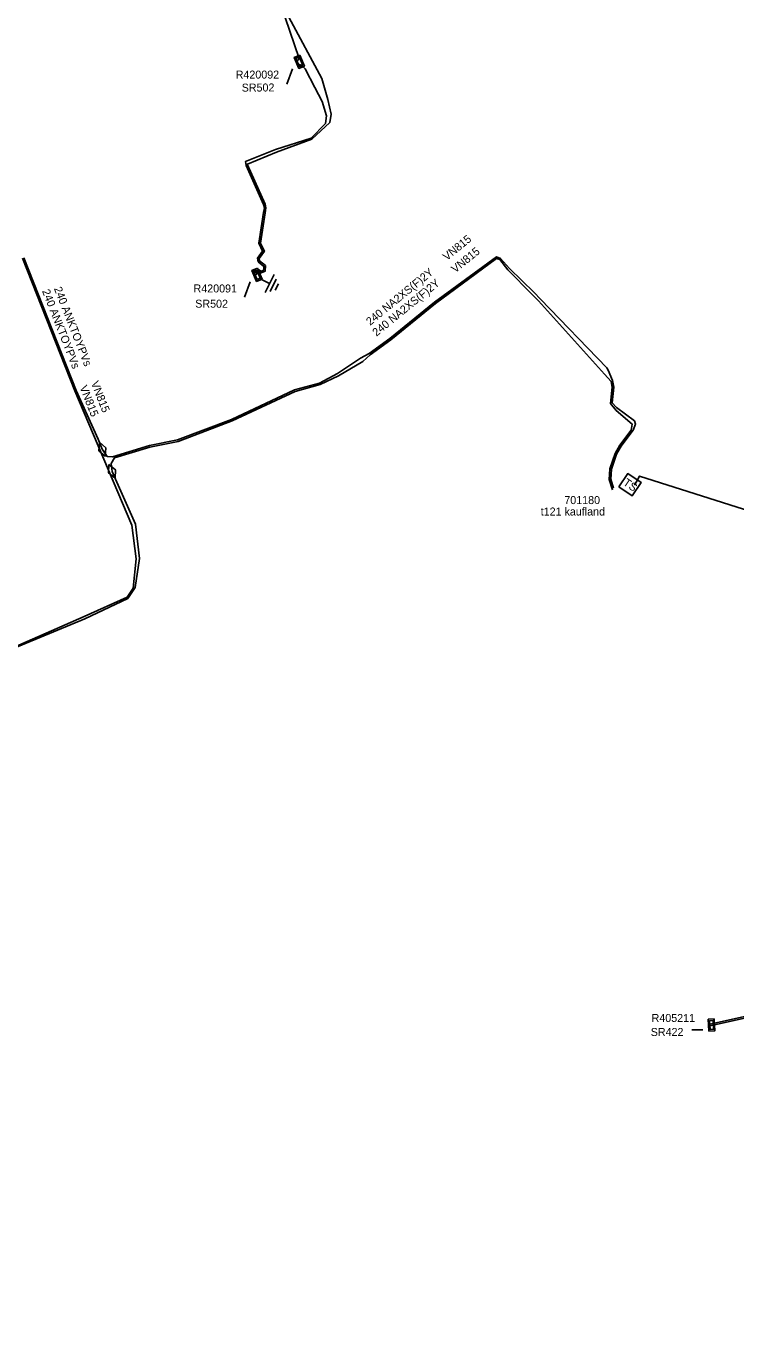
# Model space of a CAD drawing. Extents: x -540028 to -538776, y -1157064 to -1155670.
# Drawn here: x -539454.6 to -539365.9, y -1156092.2 to -1155928.9 of the extents above; entities that cross this region are included whole.
import ezdxf

# ---------------------------------------------------------------- set-up
doc = ezdxf.new("R2010")
doc.units = 0
for name, color, linetype in [('Vrstva 15', 7, 'Continuous'), ('Vrstva 19', 7, 'Continuous'), ('Vrstva 2', 7, 'Continuous'), ('Vrstva 25', 7, 'Continuous'), ('Vrstva 26', 7, 'Continuous'), ('Vrstva 27', 7, 'Continuous'), ('Vrstva 28', 7, 'Continuous'), ('Vrstva 29', 7, 'Continuous'), ('Vrstva 30', 7, 'Continuous'), ('Vrstva 5', 7, 'Continuous'), ('Vrstva 59', 7, 'Continuous'), ('Vrstva 6', 7, 'Continuous'), ('Vrstva 7', 7, 'Continuous')]:
    doc.layers.add(name, color=color, linetype=linetype)

# ---------------------------------------------------------------- blocks, each defined once
blk = doc.blocks.new('17')
at = {"layer": 'Vrstva 2'}
blk.add_lwpolyline([(-1.875, 0), (0, 0.9375), (1.875, 0), (0, -0.9375)], close=True, dxfattribs=at)
blk = doc.blocks.new('30')
at = {"layer": 'Vrstva 2'}
blk.add_lwpolyline([(-2, 0), (2, 0), (2, 4), (-2, 4)], close=True, dxfattribs=at)
blk.add_text('TS', height=2, dxfattribs=at).set_placement((-1.598, 1))
blk = doc.blocks.new('132')
at = {"layer": 'Vrstva 2'}
for points in [[(-1.5, 1.5), (1.5, 1.5), (1.5, 0), (-1.5, 0)], [(-1.1, 1.2), (1.1, 1.2), (1.1, 0.3), (-1.1, 0.3)]]:
    blk.add_lwpolyline(points, close=True, dxfattribs=at)
blk = doc.blocks.new('11')
at = {"layer": 'Vrstva 2'}
for p, q in [((0, -4.3), (0, -1.3)), ((-2.5, -4.3), (2.5, -4.3)), ((-1.7, -5.3), (1.7, -5.3)), ((-0.9, -6.3), (0.9, -6.3))]:
    blk.add_line(p, q, dxfattribs=at)

msp = doc.modelspace()

# ---------------------------------------------------------------- linework, layer by layer
at = {"layer": 'Vrstva 5'}
for points in [[(-539452.8, -1155875.66), (-539450.82, -1155874.95), (-539449.64, -1155875.25), (-539448.74, -1155876.15), (-539446.18, -1155879.34), (-539444.99, -1155881.07), (-539444.21, -1155882.24), (-539443.31, -1155882.35), (-539440.32, -1155884.14), (-539437.56, -1155889.45), (-539434.08, -1155893.05), (-539432.51, -1155896.62), (-539432.27, -1155900.84), (-539432.34, -1155906.73), (-539431.9, -1155910.33), (-539429.95, -1155914.18), (-539428.63, -1155916.07), (-539426.67, -1155918.3), (-539425.12, -1155920.72), (-539422.21, -1155927.83), (-539420.46, -1155932.98), (-539420.81, -1155933.39)], [(-539421.77, -1155927.78), (-539417.65, -1155935.45), (-539416.87, -1155938.1), (-539416.45, -1155939.92), (-539416.64, -1155940.95), (-539418.89, -1155943.06), (-539423.28, -1155944.68), (-539426.93, -1155946.15), (-539426.91, -1155946.27), (-539424.73, -1155951.16), (-539424.62, -1155951.63), (-539424.72, -1155952.24), (-539425.32, -1155956.02), (-539424.81, -1155957.05), (-539425.46, -1155957.95), (-539425.41, -1155958.26), (-539424.68, -1155958.85), (-539424.7, -1155959.53), (-539425.21, -1155959.76), (-539425.53, -1155959.59), (-539426.03, -1155960.2)], [(-539420.71, -1155933.64), (-539420.11, -1155933.82), (-539419.72, -1155934.24), (-539418.52, -1155936.57), (-539417.59, -1155938.33), (-539417.04, -1155940.13), (-539417.19, -1155941.07), (-539418.95, -1155942.9), (-539423.44, -1155944.33), (-539427.16, -1155945.83), (-539427.11, -1155946.33), (-539424.93, -1155951.22), (-539424.82, -1155951.63), (-539424.92, -1155952.2), (-539425.52, -1155956.04), (-539425.05, -1155957.03), (-539425.68, -1155957.91), (-539425.59, -1155958.36), (-539424.88, -1155958.95), (-539424.9, -1155959.4), (-539425.21, -1155959.54), (-539425.52, -1155959.37), (-539426.18, -1155959.86)], [(-539455.04, -1155957.9), (-539448.51, -1155974.5), (-539441.37, -1155991.27), (-539440.83, -1155995.51), (-539441.22, -1155999.18), (-539441.98, -1156000.3), (-539447.36, -1156002.72), (-539460.3, -1156008.35)], [(-539454.88, -1155957.87), (-539448.36, -1155974.45), (-539445.59, -1155980.55), (-539445.08, -1155981.8)], [(-539445.08, -1155981.8), (-539444.48, -1155982.7), (-539443.79, -1155982.74), (-539439.18, -1155981.33), (-539435.67, -1155980.63), (-539428.94, -1155978.08), (-539421.05, -1155974.39), (-539417.92, -1155973.54), (-539415.68, -1155972.35), (-539412.78, -1155970.42), (-539411.71, -1155969.84), (-539409.14, -1155967.96), (-539403.56, -1155963.41), (-539395.82, -1155957.74), (-539395.28, -1155957.94), (-539394.17, -1155959.19), (-539391.1, -1155962.21), (-539390.31, -1155963.02), (-539382.02, -1155971.62), (-539381.84, -1155971.93), (-539381.28, -1155973.21), (-539381.14, -1155974.05), (-539381.33, -1155976.01), (-539380.81, -1155976.58), (-539378.54, -1155978.25), (-539378.43, -1155978.66), (-539378.73, -1155979.42), (-539380.22, -1155981.42), (-539380.79, -1155982.42), (-539381.43, -1155984.29), (-539381.51, -1155985.54), (-539381.16, -1155986.66)], [(-539443.86, -1155984.56), (-539443.95, -1155983.58), (-539443.57, -1155982.89), (-539439.14, -1155981.53), (-539435.61, -1155980.83), (-539428.86, -1155978.26), (-539420.97, -1155974.57), (-539417.84, -1155973.72), (-539415.54, -1155972.61), (-539412.51, -1155970.81), (-539411.6, -1155970), (-539409.02, -1155968.12), (-539403.44, -1155963.57), (-539395.78, -1155957.96), (-539395.4, -1155958.1), (-539394.38, -1155959.39), (-539391.33, -1155962.44), (-539390.57, -1155963.24), (-539389.78, -1155964.07), (-539382.32, -1155972.4), (-539381.46, -1155973.31), (-539381.34, -1155974.05), (-539381.53, -1155976.07), (-539380.84, -1155976.95), (-539378.86, -1155978.66), (-539378.98, -1155979.42), (-539380.38, -1155981.3), (-539380.97, -1155982.34), (-539381.63, -1155984.25), (-539381.71, -1155985.56), (-539381.3, -1155986.87)], [(-539443.86, -1155984.56), (-539443.6, -1155985.15), (-539440.92, -1155991.16), (-539440.42, -1155995.44), (-539440.97, -1155999.09), (-539441.89, -1156000.45), (-539447.27, -1156002.99), (-539460.28, -1156008.35), (-539470.34, -1156012.41), (-539476.49, -1156015.06), (-539485.51, -1156019.11), (-539499.24, -1156025.18), (-539499.2, -1156027.51), (-539498.67, -1156029.88), (-539496.3, -1156035.57), (-539495.25, -1156039.55)], [(-539250.22, -1156092.08), (-539250.99, -1156091.41), (-539258.46, -1156088.02), (-539275.21, -1156080.7), (-539300.15, -1156069.26), (-539303.1, -1156067.91), (-539303.12, -1156066.16), (-539301.78, -1156063.26), (-539301.32, -1156060.67), (-539303.45, -1156058.22), (-539315.54, -1156049.78), (-539322.53, -1156044.66), (-539325.41, -1156043.7), (-539331.77, -1156039.86), (-539338.8, -1156040.27), (-539345.04, -1156044.15), (-539355.02, -1156052.94), (-539364.61, -1156052.65), (-539369.29, -1156053.68)], [(-539250.34, -1156092.24), (-539251.1, -1156091.58), (-539258.54, -1156088.2), (-539275.29, -1156080.88), (-539300.23, -1156069.44), (-539303.3, -1156068.03), (-539303.32, -1156066.12), (-539301.98, -1156063.2), (-539301.54, -1156060.73), (-539303.59, -1156058.37), (-539315.66, -1156049.94), (-539322.63, -1156044.84), (-539325.49, -1156043.88), (-539331.83, -1156040.06), (-539338.74, -1156040.47), (-539344.92, -1156044.31), (-539354.94, -1156053.14), (-539364.57, -1156052.85), (-539369.28, -1156053.89)]]:
    msp.add_lwpolyline(points, dxfattribs=at)
at = {"layer": 'Vrstva 59'}
for points in [[(-539421.28, -1155934.27), (-539422, -1155936.15)], [(-539426.59, -1155960.89), (-539427.3, -1155962.77)], [(-539378.56, -1155986.3), (-539377.92, -1155985.15), (-539350.23, -1155993.94), (-539343.82, -1155998.7)], [(-539370.01, -1156054.36), (-539371.4, -1156054.35)]]:
    msp.add_lwpolyline(points, dxfattribs=at)

# ---------------------------------------------------------------- block references
at = {"layer": 'Vrstva 15', "xscale": 0.5, "yscale": 0.5, "rotation": 64.00639450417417}
msp.add_blockref('11', (-539426.09, -1155960.14), dxfattribs=at)
at = {"layer": 'Vrstva 19'}
for p, xscale, yscale, rotation in [((-539445.08, -1155981.8), 0.5000000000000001, 0.5, -67.80454167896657), ((-539443.86, -1155984.56), 0.49999999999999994, 0.5000000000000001, -66.05553335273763)]:
    msp.add_blockref('17', p, dxfattribs=dict(at, xscale=xscale, yscale=yscale, rotation=rotation))
at = {"layer": 'Vrstva 25', "xscale": 0.5, "yscale": 0.5, "rotation": -33.63697776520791}
msp.add_blockref('30', (-539379.67, -1155987.05), dxfattribs=at)
at = {"layer": 'Vrstva 28', "xscale": 0.5, "yscale": 0.5}
for p, rotation in [((-539420.79, -1155933.51), -67.16696668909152), ((-539426.09, -1155960.14), -67.0030388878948), ((-539369.29, -1156053.78), -86.68391109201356)]:
    msp.add_blockref('132', p, dxfattribs=dict(at, rotation=rotation))

# ---------------------------------------------------------------- texts
at = {"layer": 'Vrstva 26'}
msp.add_text('701180', height=1, dxfattribs=at).set_placement((-539387.32, -1155988.65))
at = {"layer": 'Vrstva 27'}
msp.add_text('t121 kaufland', height=1, dxfattribs=at).set_placement((-539390.27, -1155990.08))
at = {"layer": 'Vrstva 29'}
for s, p in [('R420092', (-539428.4, -1155935.47)), ('R420091', (-539433.67, -1155962.2)), ('R405211', (-539376.41, -1156053.38))]:
    msp.add_text(s, height=1, dxfattribs=at).set_placement(p)
at = {"layer": 'Vrstva 30'}
for rotation, p in [(0.319, (-539427.65, -1155937.1)), (359.819, (-539433.46, -1155964.1))]:
    msp.add_text('SR502', height=1, rotation=rotation, dxfattribs=at).set_placement(p)
msp.add_text('SR422', height=1, dxfattribs=at).set_placement((-539376.52, -1156055.13))
at = {"layer": 'Vrstva 6'}
for s, rotation, p in [('240 NA2XS(F)2Y', 39.194, (-539411.6, -1155966.38)), ('240 ANKTOYPVs', 291.49, (-539452.63, -1155962.02)), ('240 ANKTOYPVs', 291.471, (-539451.14, -1155961.71)), ('240 NA2XS(F)2Y', 39.194, (-539410.81, -1155967.74))]:
    msp.add_text(s, height=1, rotation=rotation, dxfattribs=at).set_placement(p)
at = {"layer": 'Vrstva 7'}
for rotation, p in [(39.194, (-539402.01, -1155958.28)), (39.194, (-539400.95, -1155959.82)), (291.471, (-539446.52, -1155973.51)), (291.49, (-539447.93, -1155974.04))]:
    msp.add_text('VN815', height=1, rotation=rotation, dxfattribs=at).set_placement(p)

doc.saveas('drawing.dxf')
